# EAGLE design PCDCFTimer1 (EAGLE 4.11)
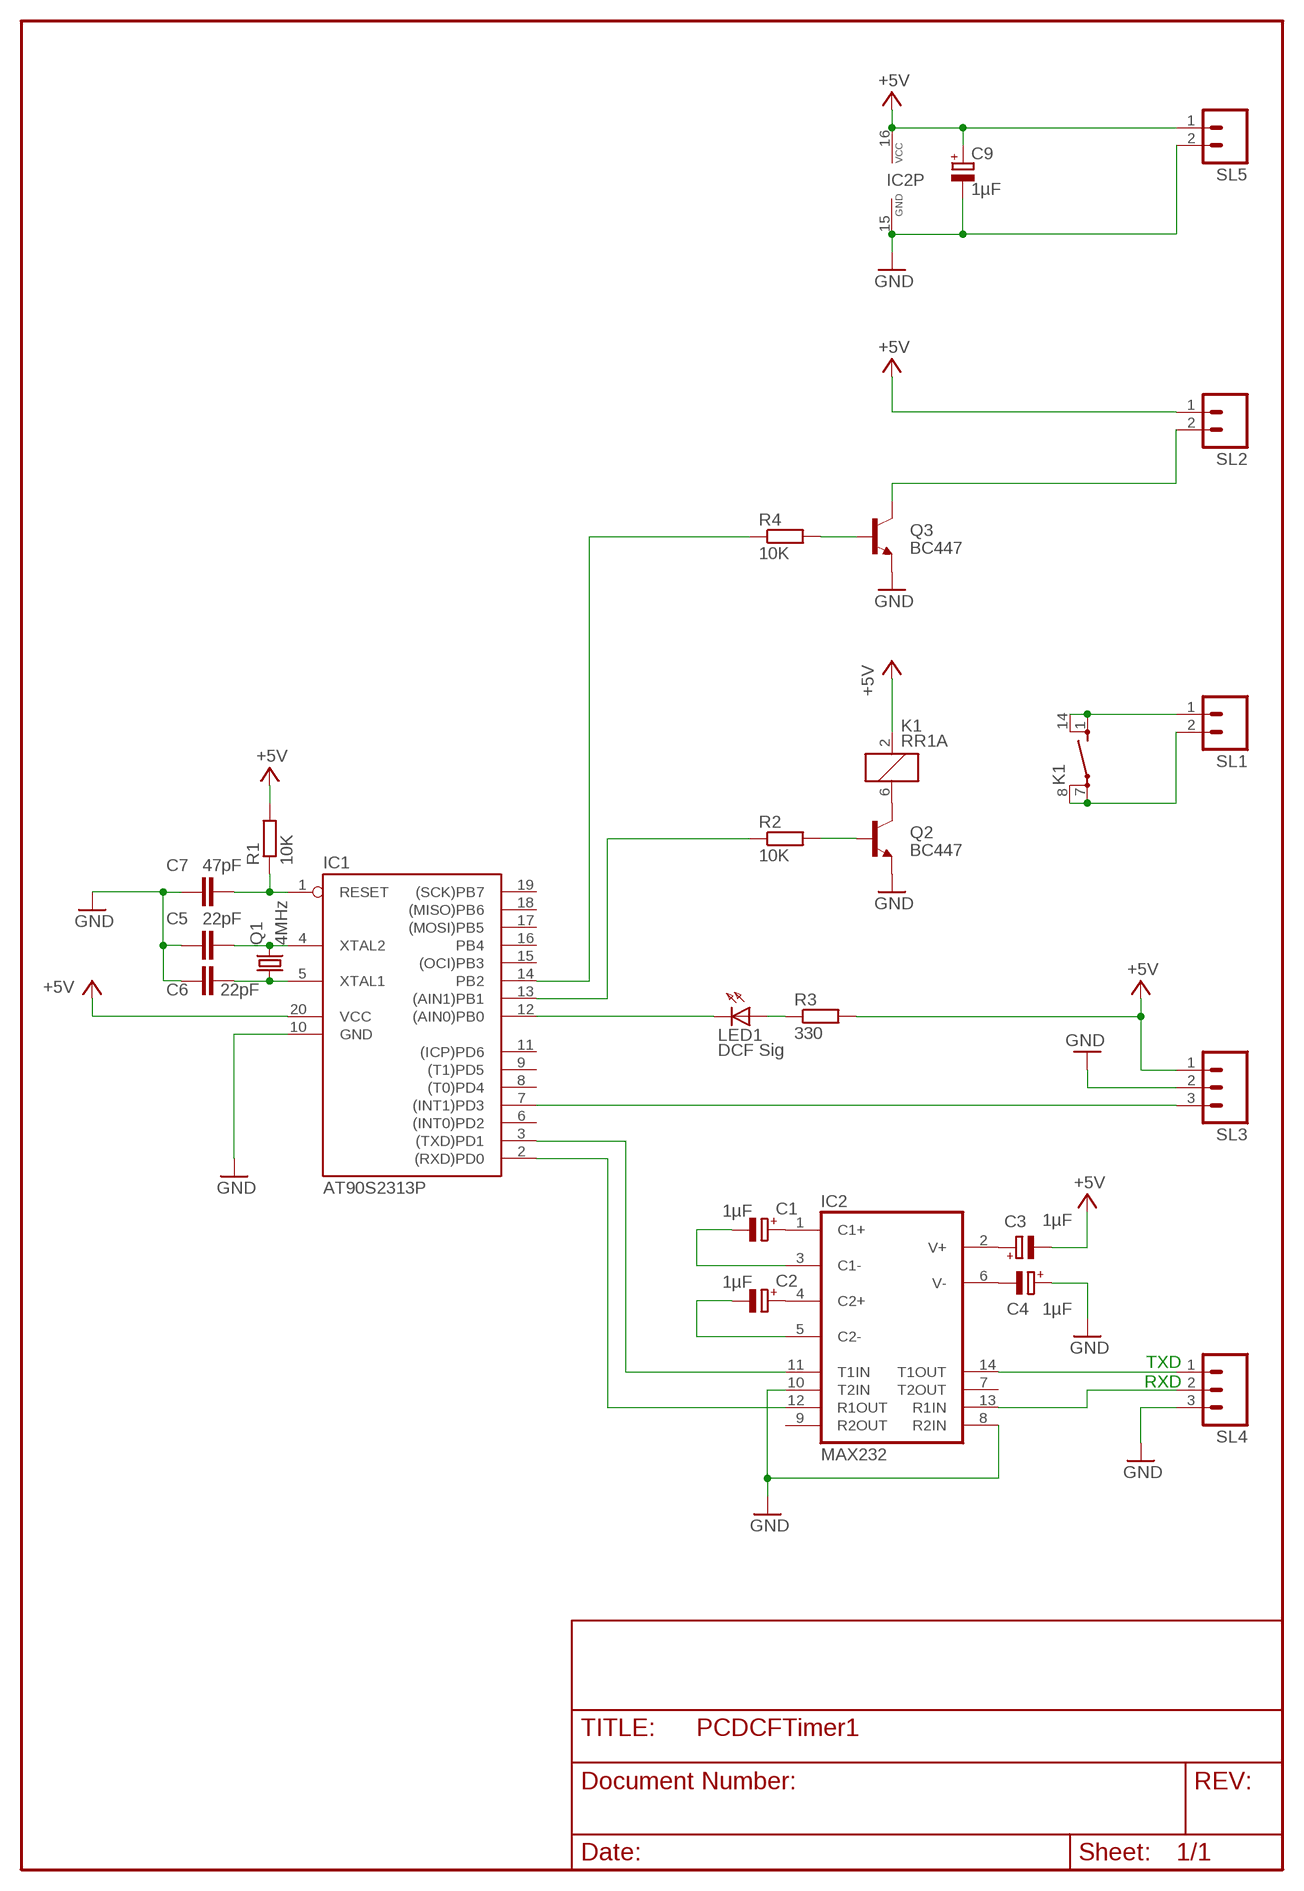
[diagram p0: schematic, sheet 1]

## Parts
C1  1µF  CPOL-EUE2.5-5  [E2,5-5]
C2  1µF  CPOL-EUE2.5-5  [E2,5-5]
C3  1µF  CPOL-EUE2.5-5  [E2,5-5]
C4  1µF  CPOL-EUE2.5-5  [E2,5-5]
C5  22pF  C-EU025-024X044  [C025-024X044]
C6  22pF  C-EU025-024X044  [C025-024X044]
C7  47pF  C-EU025-024X044  [C025-024X044]
C9  1µF  CPOL-EUE2.5-5  [E2,5-5]
IC1  AT90S2313P  [DIL20]
IC2  MAX232  [DIL16]
K1  RR1A  [RR1A]
LED1  DCF Sig  LED3MM  [LED3MM]
Q1  4MHz  CRYTALHC18U-V  [HC18U-V]
Q2  BC447  [TO92-EBC]
Q3  BC447  [TO92-EBC]
R1  10K  R-EU_0204/7  [0204/7]
R2  10K  R-EU_0204/7  [0204/7]
R3  330  R-EU_0204/7  [0204/7]
R4  10K  R-EU_0204/7  [0204/7]
SL1  M02  [02P]
SL2  M02  [02P]
SL3  M03  [03P]
SL4  M03  [03P]
SL5  M02  [02P]

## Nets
+5V: C3.- C9.+ IC1.20(VCC) IC2.16(VCC) K1.2 R1.2 R3.2 SL2.1 SL3.1 SL5.1
GND: C4.+ C5.1 C6.1 C7.1 C9.- IC1.10(GND) IC2.8(R2IN) IC2.10(T2IN) IC2.15(GND) Q2.E Q3.E SL3.2 SL4.3 SL5.2
N$1: C1.+ IC2.1(C1+)
N$2: C1.- IC2.3(C1-)
N$3: C2.+ IC2.4(C2+)
N$4: C2.- IC2.5(C2-)
N$5: C3.+ IC2.2(V+)
N$6: C4.- IC2.6(V-)
N$7: IC2.14(T1OUT) SL4.1
N$8: IC2.13(R1IN) SL4.2
N$9: IC1.3((TXD)PD1) IC2.11(T1IN)
N$10: IC1.13((AIN1)PB1) R2.1
N$11: C5.2 IC1.4(XTAL2) Q1.2
N$12: C6.2 IC1.5(XTAL1) Q1.1
N$13: K1.6 Q2.C
N$14: C7.2 IC1.1(RESET) R1.1
N$15: Q2.B R2.2
N$17: IC1.12((AIN0)PB0) LED1.K(C)
N$19: LED1.A R3.1
N$21: K1.1(2:S) K1.14(2:S) SL1.1
N$22: IC1.2((RXD)PD0) IC2.12(R1OUT)
N$23: Q3.B R4.2
N$24: Q3.C SL2.2
N$25: IC1.7((INT1)PD3) SL3.3
N$26: IC1.14(PB2) R4.1
N$29: K1.7(2:P) K1.8(2:P) SL1.2
Unconnected: IC1.6((INT0)PD2) IC1.8((T0)PD4) IC1.9((T1)PD5) IC1.11((ICP)PD6) IC1.15((OCI)PB3) IC1.16(PB4) IC1.17((MOSI)PB5) IC1.18((MISO)PB6) IC1.19((SCK)PB7) IC2.7(T2OUT) IC2.9(R2OUT)

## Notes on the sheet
- TXD
- RXD

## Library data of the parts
C1-C4 C9 = rcl:CPOL-EU: POLARIZED CAPACITOR, European symbol
C5-C7 = rcl:C-EU: CAPACITOR, European symbol
IC1 = atmel:AT90S2313: MICROCONTROLLER 2 Kbytes FLASH 128 bytes SRAM 128 bytes EEPROM UART
IC2 = maxim:MAX232: RS232 TRANSEIVER
K1 = relay:RR1A: RELAY reed, polarity, 1 x norm. open with shield
LED1 = led:LED: LED
Q1 = crystal:CRYTAL: CRYSTAL
Q2 Q3 = transistor-npn:BC447*: NPN Transistor
R1-R4 = rcl:R-EU_: RESISTOR, European symbol
SL1 SL2 SL5 = con-amp-quick:M02: AMP QUICK CONNECTOR
SL3 SL4 = con-amp-quick:M03: AMP QUICK CONNECTOR

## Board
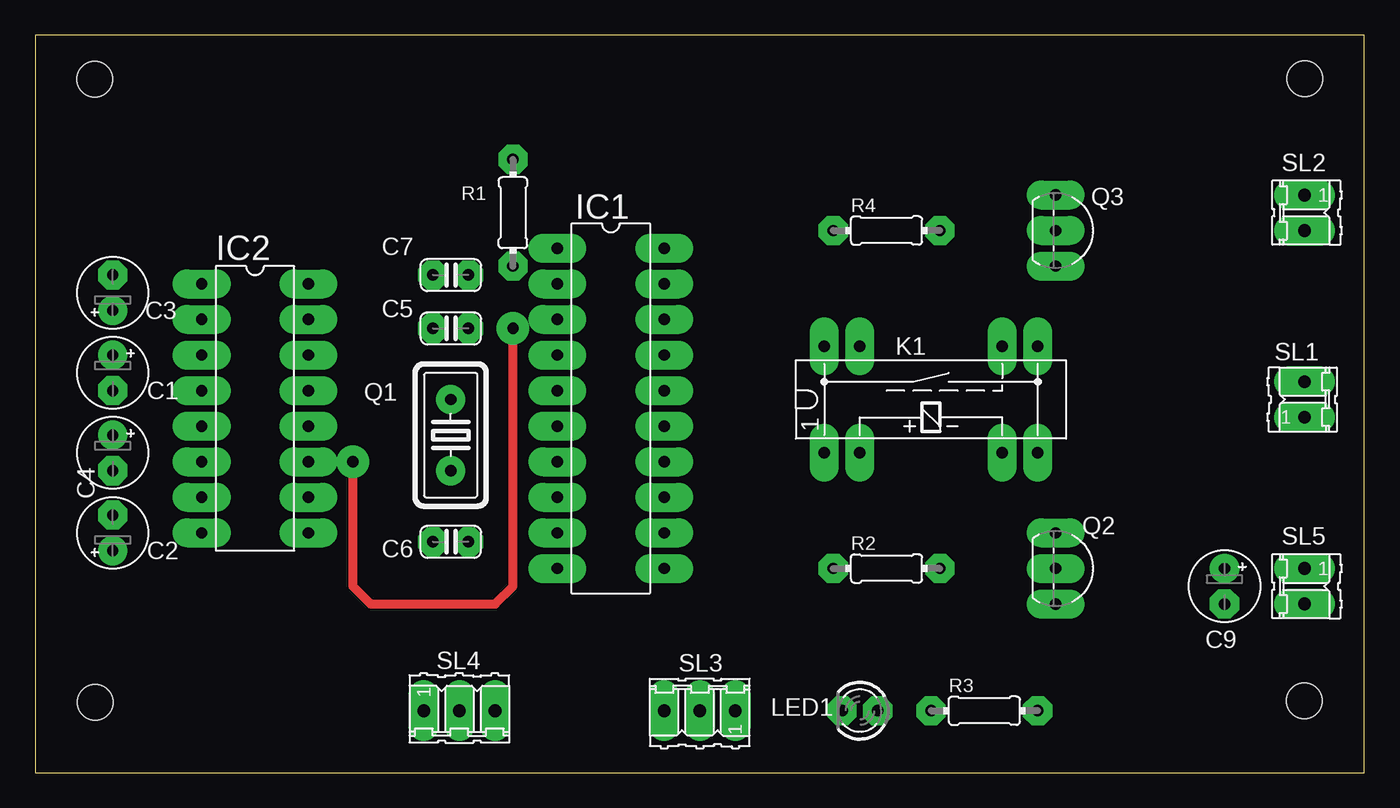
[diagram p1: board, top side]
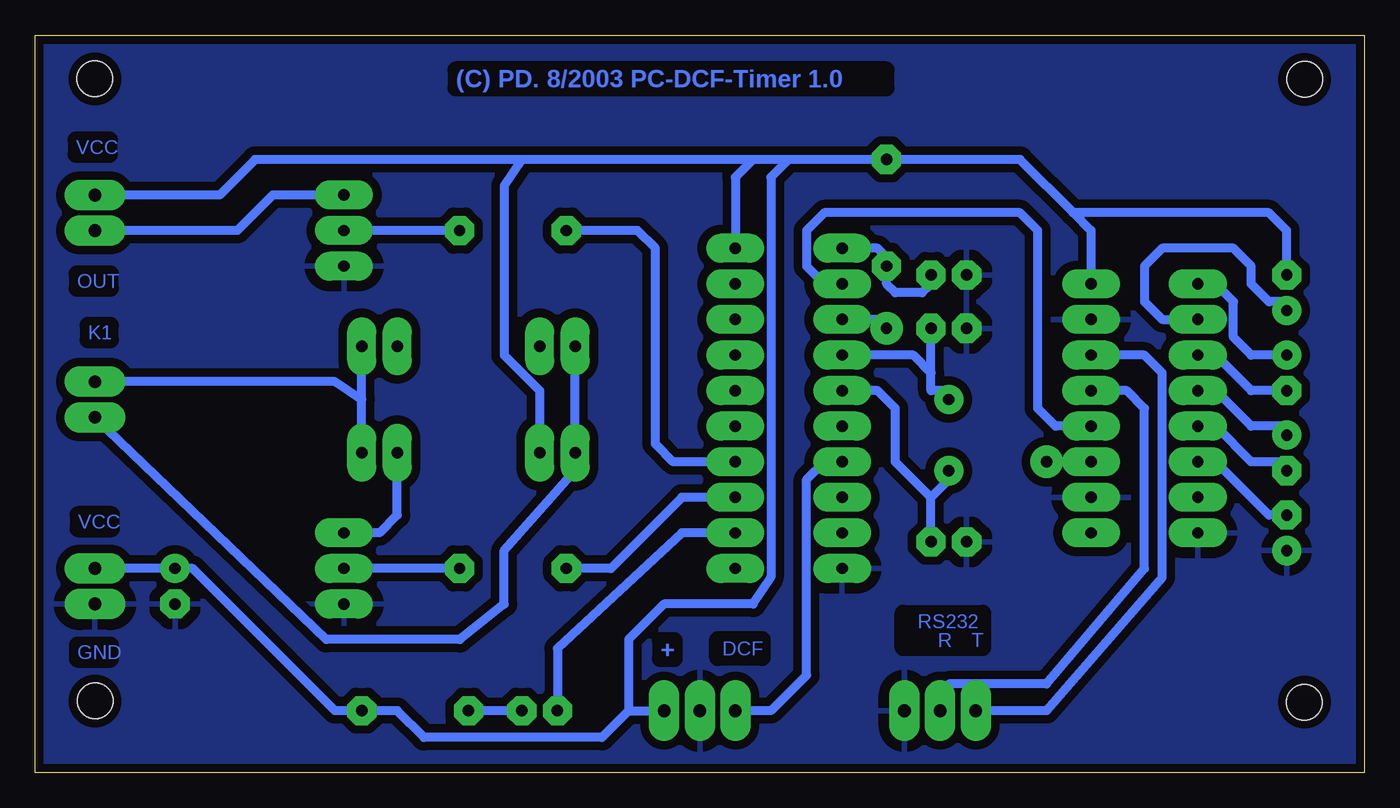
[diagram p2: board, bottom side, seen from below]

Size 94.92 x 52.7 mm. Coordinates in mm from the lower left corner, seen from the top.
Outline: 0,0 94.92,0 94.92,52.7 0,52.7 0,0
Copper layers (1*16): Top 0.035mm / dielectric 1.5mm / Bottom 0.035mm
Design rules "default": minimum track width 25mil, minimum drill 0.0051mm, track to track 8mil, track to pad 8mil, pad to pad 8mil, via to via 8mil, smd to smd 8mil, copper to edge 10mil, drill to drill 0.2mm, minimum pad ring 25mil, minimum via ring 30mil, stop-mask expansion 4mil, vias tented up to drill 0mil, thermal gap 30mil
Holes 2.54 mm at 4.28,5.05 90.64,5.13 90.64,49.56 4.27,49.52
tRestrict: area 3,15.2 to 19.5,44.4; area 25.2,14 to 33.5,41.3; area 36,12.1 to 46.2,40.6; area 53.8,21.6 to 73.5,31.7; area 54.4,14 to 68.4,16.5; area 25.9,1.9 to 34.7,7.6; area 43,1.9 to 51.3,7.6; area 57,1.9 to 60.8,6.3; area 64,2.5 to 72.9,5.7; area 56.3,38.1 to 65.2,40; area 56.3,14 to 65.2,15.2; area 71.6,11.4 to 74.1,17.8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
bRestrict: area 27.3,8.9 to 33,11.4; area 43,8.2 to 46.2,9.5

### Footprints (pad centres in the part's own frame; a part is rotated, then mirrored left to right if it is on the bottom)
E2,5-5 = drill 0.813 pad 1.6 round: + -1.27,0 | drill 0.813 pad 1.6 octagon: - 1.27,0
C025-024X044 = drill 0.813 octagon: 1 -1.27,0; 2 1.27,0
DIL20 = drill 0.813 long: 1 -11.43,-3.81; 2 -8.89,-3.81; 3 -6.35,-3.81; 4 -3.81,-3.81; 5 -1.27,-3.81; 6 1.27,-3.81; 7 3.81,-3.81; 8 6.35,-3.81; 9 8.89,-3.81; 10 11.43,-3.81; 11 11.43,3.81; 12 8.89,3.81; 13 6.35,3.81; 14 3.81,3.81; 15 1.27,3.81; 16 -1.27,3.81; 17 -3.81,3.81; 18 -6.35,3.81; 19 -8.89,3.81; 20 -11.43,3.81
DIL16 = drill 0.813 long: 1 -8.89,-3.81; 2 -6.35,-3.81; 3 -3.81,-3.81; 4 -1.27,-3.81; 5 1.27,-3.81; 6 3.81,-3.81; 7 6.35,-3.81; 8 8.89,-3.81; 9 8.89,3.81; 10 6.35,3.81; 11 3.81,3.81; 12 1.27,3.81; 13 -1.27,3.81; 14 -3.81,3.81; 15 -6.35,3.81; 16 -8.89,3.81
RR1A = drill 0.813 long: 1 -7.62,-3.81; 2 -5.08,-3.81; 6 5.08,-3.81; 7 7.62,-3.81; 8 7.62,3.81; 9 5.08,3.81; 13 -5.08,3.81; 14 -7.62,3.81
LED3MM = drill 0.813 octagon: A -1.27,0; K 1.27,0
HC18U-V = drill 0.813 round: 1 -2.54,0; 2 2.54,0
TO92-EBC = drill 0.813 long: B 0,-1.27; C -2.54,-1.27; E 2.54,-1.27
0204/7 = drill 0.813 octagon: 1 -3.81,0; 2 3.81,0
02P = drill 0.914 long: 1 -1.27,0; 2 1.27,0
03P = drill 0.914 long: 1 -2.54,0; 2 0,0; 3 2.54,0

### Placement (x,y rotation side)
C1  5.55,28.57 270 top
C2  5.55,22.85 270 top
C3  5.55,34.28 90 top
C4  5.55,17.14 90 top
C5  29.68,31.74 0 top
C6  29.68,16.5 0 top
C7  29.68,35.55 0 top
C9  84.92,13.33 270 top
IC1  41.11,26.03 270 top
IC2  15.71,26.03 270 top
K1  63.97,26.66 0 top
LED1  58.89,4.44 180 top
Q1  29.68,24.12 90 top
Q2  74.13,14.6 270 top
Q3  74.13,38.73 270 top
R1  34.12,40 90 top
R2  60.8,14.6 0 top
R3  67.78,4.44 0 top
R4  60.8,38.73 0 top
SL1  90.64,26.66 90 top
SL2  90.64,40 270 top
SL3  47.46,4.44 180 top
SL4  30.3,4.44 0 top
SL5  90.64,13.33 270 top

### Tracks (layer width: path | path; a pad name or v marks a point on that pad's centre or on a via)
+5V
  Bottom 0.635: 52.54,4.44 54.45,2.54 67.14,2.54 69.05,4.44 R3.2 73.5,4.44 83.66,14.6 C9.+ SL5.1 | 60.16,43.81 61.43,41.91 61.43,29.84 58.89,27.3 K1.2 | 41.11,43.81 43.65,43.81 | 43.65,43.81 60.16,43.81 | 41.11,43.81 R1.2 24.6,43.81 20.79,40 | IC2.16 19.52,38.73 20.79,40 | 20.79,40 6.82,40 5.55,38.73 C3.- | 43.65,43.81 44.92,42.54 IC1.20 | 52.54,4.44 52.54,9.52 50,12.06 43.65,12.06 42.38,13.96 42.38,42.54 41.11,43.81 | 52.54,4.44 SL3.1 | SL2.1 81.75,41.27 79.21,43.81 60.16,43.81
GND
  pour Bottom (isolate 0.61): 0.47,0.63 94.45,0.63 94.45,53.34 0.47,53.34
N$1
  Bottom 0.635: C1.+ 8.09,29.84 9.36,31.11 9.36,33.65 10.63,34.92 IC2.1
N$2
  Bottom 0.635: C1.- 8.09,27.3 10.63,29.84 IC2.3
N$3
  Bottom 0.635: IC2.4 10.63,27.3 8.09,24.76 5.55,24.76 C2.+
N$4
  Bottom 0.635: IC2.5 10.63,24.76 8.09,22.22 5.55,22.22 C2.-
N$5
  Bottom 0.635: IC2.2 14.44,32.38 15.71,33.65 15.71,36.19 14.44,37.46 9.36,37.46 8.09,36.19 8.09,34.92 6.82,33.65 5.55,33.65 C3.+
N$6
  Bottom 0.635: C4.- 6.82,18.41 10.63,22.22 IC2.6
N$7
  Bottom 0.635: SL4.1 22.7,4.44 14.44,13.96 14.44,28.57 15.71,29.84 IC2.14
N$8
  Bottom 0.635: IC2.13 16.98,27.3 15.71,26.03 15.71,14.6 22.7,6.35 29.66,6.35 30.3,5.71 SL4.2
N$9  (via drill 0.8 pad 2)
  Top 0.635: v22.7,22.22 22.7,13.33 23.96,12.06 32.86,12.06 34.12,13.33 v34.12,31.74
  Bottom 0.635: v22.7,22.22 IC2.11 | v34.12,31.74 34.76,32.38 IC1.3
N$10
  Bottom 0.635: R2.1 53.81,14.6 48.73,19.68 IC1.13
N$11
  Bottom 0.635: 30.95,28.57 30.95,27.3 29.68,27.3 Q1.2 | 30.95,28.57 C5.2 | 30.95,28.57 32.22,29.84 IC1.4
N$12
  Bottom 0.635: 30.95,19.68 29.68,20.95 Q1.1 | C6.2 30.95,19.68 | 30.95,19.68 33.49,22.22 33.49,26.03 34.76,27.3 IC1.5
N$13
  Bottom 0.635: Q2.C 70.32,17.14 69.05,18.41 K1.6
N$14
  Bottom 0.635: C7.2 30.95,34.92 31.58,34.28 33.49,34.28 34.12,34.92 R1.1 34.12,36.82 34.76,37.46 IC1.1
N$15
  Bottom 0.635: R2.2 Q2.B
N$17
  Bottom 0.635: LED1.K 57.62,8.88 48.73,17.14 IC1.12
N$19
  Bottom 0.635: LED1.A R3.1
N$21
  Bottom 0.635: K1.14 K1.1 56.35,21.58 61.43,15.87 61.43,12.06 64.61,9.52 74.13,9.52 SL1.1
N$22
  Bottom 0.635: IC2.12 22.06,24.76 23.33,26.03 23.33,38.73 24.6,40 38.57,40 39.84,38.73 39.84,36.19 38.57,34.92 IC1.2
N$23
  Bottom 0.635: R4.2 Q3.B
N$24
  Bottom 0.635: SL2.2 80.48,38.73 77.94,41.27 Q3.C
N$25
  Bottom 0.635: SL3.3 42.38,4.44 39.84,6.98 39.84,20.95 38.57,22.22 IC1.7
N$26
  Bottom 0.635: IC1.14 49.37,22.22 50.64,23.49 50.64,37.46 51.91,38.73 R4.1
N$29
  Bottom 0.635: K1.7 71.59,26.66 | 71.59,26.66 K1.8 | 71.59,26.66 73.5,27.93 SL1.2

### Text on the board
Bottom: (C) PD. 8/2003 PC-DCF-Timer 1.0 | VCC | OUT | K1 | VCC | RS232 | T | R | DCF | + | GND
